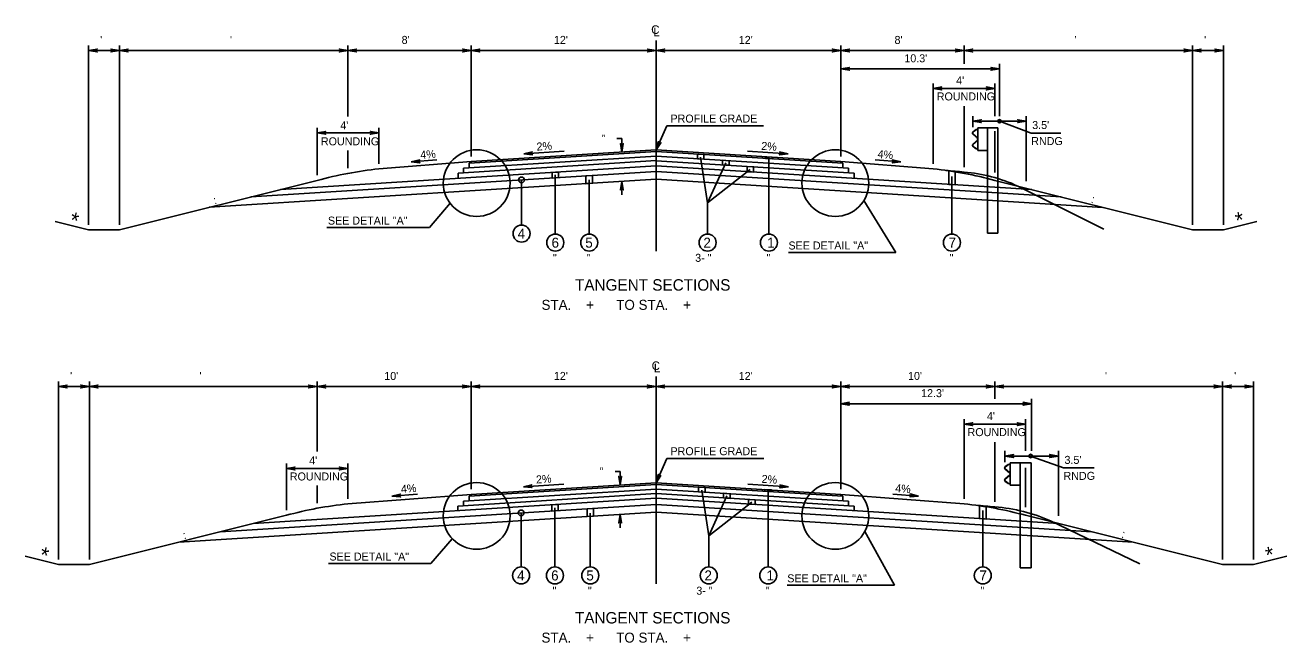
# Model space of a CAD drawing. Extents: x -540 to 1231, y -564 to 421.
# Drawn here: x 173.2 to 393.9, y -310 to -201.9 of the extents above; entities that cross this region are included whole.
import ezdxf

# ---------------------------------------------------------------- set-up
doc = ezdxf.new("R2010")
doc.units = 0
doc.layers.add('1', color=7, linetype='Continuous')
doc.layers.add('Des_ Drain_ Ftrs', color=7, linetype='Continuous')

msp = doc.modelspace()

# ---------------------------------------------------------------- linework, layer by layer
at = {"layer": '1'}
for p, q in [((283.58, -241.47), (283.58, -204.59)), ((184.34, -236.84), (184.34, -205.47)), ((189.73, -206.35), (184.34, -206.35)), ((189.73, -236.84), (189.73, -205.47)), ((229.69, -206.35), (189.73, -206.35)), ((229.69, -217.88), (229.69, -205.47)), ((251.25, -206.35), (229.69, -206.35)), ((251.25, -224.9), (251.25, -205.47)), ((283.58, -206.35), (251.25, -206.35)), ((283.58, -206.35), (315.91, -206.35)), ((315.91, -224.9), (315.91, -205.47)), ((315.91, -206.35), (337.46, -206.35)), ((337.46, -208.69), (337.46, -205.47)), ((337.46, -206.35), (377.42, -206.35)), ((377.42, -236.85), (377.42, -205.47)), ((377.42, -206.35), (382.81, -206.35)), ((382.81, -236.85), (382.81, -205.47)), ((315.9, -209.57), (343.65, -209.57)), ((343.65, -217.85), (343.65, -208.69)), ((332.07, -226.2), (332.07, -212.11)), ((332.07, -212.99), (342.85, -212.99)), ((342.85, -217.85), (342.85, -212.11)), ((337.46, -226.76), (337.46, -216.11)), ((338.96, -219.8), (338.96, -217.85)), ((348.34, -229.21), (348.34, -217.85)), ((224.32, -228.2), (224.32, -219.89)), ((235.09, -226.19), (235.09, -219.89)), ((283.58, -223.75), (285.48, -219.56)), ((302.4, -219.56), (285.48, -219.56)), ((338.96, -218.73), (348.34, -218.73)), ((339.56, -220.19), (339.04, -220.58)), ((339.57, -220.22), (339.06, -220.61)), ((339.87, -220.14), (339.56, -220.19)), ((339.87, -220.17), (339.57, -220.22)), ((339.87, -219.91), (339.87, -223.84)), ((339.87, -219.91), (341.56, -219.91)), ((341.56, -219.91), (341.56, -238.31)), ((343.38, -219.91), (341.56, -219.91)), ((342.85, -227.72), (342.85, -220.48)), ((343.38, -219.91), (343.38, -238.31)), ((343.65, -218.73), (349.21, -220.8)), ((235.09, -220.77), (224.32, -220.77)), ((277.59, -221.75), (276.71, -221.75)), ((277.59, -221.75), (277.59, -224.12)), ((339.02, -221.01), (339.76, -221.65)), ((339.76, -222.1), (339.02, -222.74)), ((339.04, -220.99), (339.78, -221.63)), ((339.78, -222.12), (339.04, -222.76)), ((339.84, -221.84), (339.84, -221.91)), ((339.87, -221.84), (339.87, -221.91)), ((349.21, -220.8), (354.36, -220.8)), ((229.69, -226.97), (229.69, -223.83)), ((249.92, -226.95), (283.58, -224.84)), ((250.89, -226.1), (283.58, -224.04)), ((251.25, -225.77), (283.58, -223.74)), ((267.53, -224), (260.45, -224.44)), ((315.91, -225.78), (283.58, -223.75)), ((316.27, -226.1), (283.58, -224.04)), ((317.24, -226.96), (283.58, -224.84)), ((291.38, -225.04), (292.6, -233.04)), ((299.59, -224), (306.66, -224.45)), ((339.04, -223.17), (339.56, -223.56)), ((339.06, -223.14), (339.57, -223.53)), ((339.56, -223.56), (339.87, -223.61)), ((339.57, -223.53), (339.87, -223.58)), ((339.87, -223.84), (341.56, -223.84)), ((217.88, -230.69), (283.58, -226.56)), ((235.09, -227.07), (251.25, -225.77)), ((240.77, -225.86), (245.26, -225.5)), ((248.94, -227.81), (283.58, -225.63)), ((249.92, -226.95), (249.92, -227.75)), ((250.89, -226.1), (250.89, -226.89)), ((251.25, -226.07), (251.25, -225.77)), ((318.21, -227.82), (283.58, -225.64)), ((349.28, -230.7), (283.58, -226.56)), ((295.79, -226.02), (292.6, -233.04)), ((300.06, -227.2), (292.6, -233.04)), ((303.32, -225.14), (303.32, -238.5)), ((332.07, -227.08), (315.91, -225.78)), ((315.91, -226.08), (315.91, -225.78)), ((316.27, -226.1), (316.27, -226.88)), ((317.24, -226.96), (317.24, -227.75)), ((326.4, -225.86), (321.92, -225.5)), ((224.32, -229.08), (189.73, -237.72)), ((205.41, -233.8), (283.58, -228.89)), ((212.71, -231.98), (283.58, -227.53)), ((248.94, -227.81), (248.94, -228.74)), ((260.06, -229.01), (260.06, -236.91)), ((265.96, -228.12), (265.96, -238.5)), ((271.89, -228.97), (271.89, -238.5)), ((277.59, -229.27), (277.59, -231.64)), ((354.45, -231.99), (283.58, -227.53)), ((361.74, -233.81), (283.58, -228.89)), ((318.21, -227.82), (318.21, -228.74)), ((335.33, -228.42), (335.33, -238.5)), ((338.96, -227.86), (338.96, -227.86)), ((342.85, -229.09), (377.42, -237.73)), ((346.84, -230.09), (361.89, -237.61)), ((243.93, -237.32), (247.58, -233.1)), ((292.6, -233.04), (292.6, -238.5)), ((319.92, -232.6), (325.52, -241.68)), ((178.51, -236.26), (184.34, -237.72)), ((189.73, -237.72), (184.34, -237.72)), ((226, -237.32), (243.93, -237.32)), ((377.42, -237.73), (382.81, -237.73)), ((388.64, -236.27), (382.81, -237.73)), ((343.38, -238.31), (341.56, -238.31)), ((306.73, -241.68), (325.52, -241.68)), ((179.07, -295.43), (179.07, -264.28)), ((184.46, -295.43), (184.46, -264.28)), ((224.3, -276.52), (224.3, -264.28)), ((251.24, -283.15), (251.24, -264.28)), ((283.57, -299.71), (283.57, -263.4)), ((315.9, -283.15), (315.9, -264.28)), ((342.84, -267.29), (342.84, -264.28)), ((382.68, -295.43), (382.68, -264.28)), ((388.07, -295.43), (388.07, -264.28)), ((184.46, -265.16), (179.07, -265.16)), ((224.3, -265.16), (184.46, -265.16)), ((251.24, -265.16), (224.3, -265.16)), ((283.57, -265.16), (251.24, -265.16)), ((283.57, -265.16), (315.9, -265.16)), ((315.9, -265.16), (342.84, -265.16)), ((342.84, -265.16), (382.68, -265.16)), ((382.68, -265.16), (388.07, -265.16)), ((315.89, -268.17), (349.26, -268.17)), ((349.26, -276.44), (349.26, -267.29)), ((337.45, -284.81), (337.45, -270.86)), ((348.22, -276.44), (348.22, -270.86)), ((337.45, -271.74), (348.22, -271.74)), ((342.84, -285.35), (342.84, -274.89)), ((283.57, -281.99), (285.49, -277.76)), ((302.41, -277.76), (285.49, -277.76)), ((344.57, -278.39), (344.57, -276.44)), ((344.57, -277.32), (353.96, -277.32)), ((349.09, -277.32), (354.85, -279.4)), ((353.96, -287.81), (353.96, -276.44)), ((218.92, -286.82), (218.92, -278.62)), ((229.69, -279.5), (218.92, -279.5)), ((229.69, -284.81), (229.69, -278.62)), ((277.31, -280.02), (276.43, -280.02)), ((277.31, -280.02), (277.31, -282.39)), ((344.64, -279.61), (345.4, -280.25)), ((345.19, -278.79), (344.66, -279.18)), ((344.66, -279.59), (345.42, -280.23)), ((345.2, -278.82), (344.67, -279.2)), ((345.52, -278.74), (345.19, -278.79)), ((345.52, -278.77), (345.2, -278.82)), ((345.52, -278.51), (345.52, -282.44)), ((345.52, -278.51), (347.27, -278.51)), ((347.27, -278.51), (347.27, -296.9)), ((349.16, -278.51), (347.27, -278.51)), ((348.22, -286.27), (348.22, -279.39)), ((349.16, -278.51), (349.16, -296.9)), ((354.85, -279.4), (360.2, -279.4)), ((250.87, -284.35), (283.57, -282.29)), ((251.23, -284.03), (283.57, -281.99)), ((267.44, -282.25), (260.37, -282.69)), ((315.9, -284.03), (283.57, -281.99)), ((316.26, -284.35), (283.57, -282.29)), ((299.64, -282.27), (306.72, -282.72)), ((345.4, -280.7), (344.64, -281.33)), ((345.42, -280.72), (344.66, -281.36)), ((344.66, -281.77), (345.19, -282.16)), ((344.67, -281.74), (345.2, -282.13)), ((345.19, -282.16), (345.52, -282.21)), ((345.2, -282.13), (345.52, -282.18)), ((345.49, -280.44), (345.49, -280.51)), ((345.52, -280.44), (345.52, -280.51)), ((224.3, -285.59), (224.3, -282.47)), ((229.69, -285.69), (251.23, -284.03)), ((237.38, -284.33), (241.87, -283.98)), ((248.89, -286.09), (283.57, -283.91)), ((249.88, -285.22), (283.57, -283.1)), ((250.87, -284.35), (250.87, -285.16)), ((251.23, -284.33), (251.23, -284.03)), ((317.25, -285.22), (283.57, -283.1)), ((318.24, -286.09), (283.57, -283.91)), ((291.58, -283.32), (292.8, -291.3)), ((292.15, -282.83), (292.15, -283.64)), ((295.97, -284.3), (292.8, -291.3)), ((303.2, -283.35), (303.2, -296.74)), ((315.9, -284.33), (315.9, -284.03)), ((337.45, -285.69), (315.9, -284.03)), ((316.26, -284.35), (316.26, -285.16)), ((329.49, -284.32), (325, -283.98)), ((345.52, -282.44), (347.27, -282.44)), ((207.35, -290.59), (283.57, -285.8)), ((213.12, -289.15), (283.57, -284.72)), ((248.89, -286.09), (248.89, -286.9)), ((249.88, -285.22), (249.88, -286.03)), ((265.9, -286.41), (265.9, -296.74)), ((354.02, -289.15), (283.57, -284.72)), ((359.79, -290.59), (283.57, -285.8)), ((300.34, -285.39), (292.8, -291.3)), ((317.25, -285.22), (317.25, -286.04)), ((318.24, -286.09), (318.24, -286.91)), ((344.57, -286.45), (344.57, -286.45)), ((218.92, -287.7), (184.46, -296.31)), ((200.14, -292.39), (283.57, -287.15)), ((259.97, -287.28), (259.97, -296.74)), ((272.08, -287.33), (272.08, -296.74)), ((277.31, -287.54), (277.31, -289.91)), ((367, -292.39), (283.57, -287.15)), ((340.73, -286.86), (340.73, -296.74)), ((348.22, -287.7), (382.68, -296.31)), ((352.58, -288.69), (368.19, -296.21)), ((320.1, -290.51), (325.3, -299.94)), ((244.2, -296.12), (247.94, -291.8)), ((292.8, -291.3), (292.8, -296.74)), ((173.25, -294.85), (179.07, -296.31)), ((393.89, -294.86), (388.07, -296.31)), ((184.46, -296.31), (179.07, -296.31)), ((226.27, -296.12), (244.2, -296.12)), ((349.16, -296.9), (347.27, -296.9)), ((382.68, -296.31), (388.07, -296.31)), ((306.52, -299.94), (325.3, -299.94))]:
    msp.add_line(p, q, dxfattribs=at)
for points in [[(290.81, -224.5), (291.96, -224.57), (291.96, -225.37), (290.81, -225.29)], [(302.75, -224.95), (303.89, -225.03), (303.89, -225.32), (302.75, -225.25)], [(295.22, -225.57), (296.36, -225.64), (296.36, -226.44), (295.22, -226.37)], [(299.49, -226.64), (300.64, -226.71), (300.64, -227.64), (299.49, -227.57)], [(265.39, -227.7), (266.54, -227.63), (266.54, -228.6), (265.39, -228.67)], [(271.32, -229.66), (271.32, -228.3), (272.47, -228.23), (272.47, -229.59)], [(334.76, -227.41), (335.91, -227.59), (335.91, -229.86), (334.76, -229.78)], [(291.01, -282.76), (292.15, -282.83), (292.15, -283.64), (291.01, -283.57)], [(295.39, -283.85), (296.54, -283.92), (296.54, -284.73), (295.39, -284.66)], [(302.63, -283.19), (303.78, -283.26), (303.78, -283.56), (302.63, -283.49)], [(265.33, -285.87), (266.47, -285.79), (266.47, -286.87), (265.33, -286.95)], [(271.51, -286.56), (272.65, -286.49), (272.65, -287.83), (271.51, -287.91)], [(299.77, -284.93), (300.92, -285), (300.92, -285.81), (299.77, -285.74)], [(340.15, -286.03), (341.3, -286.2), (341.3, -288.35), (340.15, -288.28)]]:
    msp.add_lwpolyline(points, close=True, dxfattribs=at)
for centre, radius in [((343.65, -218.73), 0.3), ((252.21, -229.56), 5.84), ((314.94, -229.56), 5.84), ((260.06, -229.01), 0.5), ((260.06, -238.4), 1.49), ((265.96, -239.98), 1.49), ((271.89, -239.98), 1.49), ((292.6, -239.98), 1.49), ((303.32, -239.98), 1.49), ((335.33, -239.98), 1.49), ((252.2, -287.8), 5.84), ((314.93, -287.8), 5.84), ((259.97, -287.28), 0.5), ((259.97, -298.23), 1.49), ((265.9, -298.23), 1.49), ((272.08, -298.23), 1.49), ((292.8, -298.23), 1.49), ((303.2, -298.23), 1.49), ((340.73, -298.23), 1.49)]:
    msp.add_circle(centre, radius, dxfattribs=at)
for centre, radius, start, end in [((339.21, -220.8), 0.278, 126.9799, 229.021), ((339.21, -220.8), 0.249, 126.9799, 229.021), ((339.21, -222.95), 0.278, 130.979, 233.0201), ((339.21, -222.95), 0.249, 130.979, 233.0201), ((339.59, -221.84), 0.249, 0, 49.0365), ((339.59, -221.91), 0.249, 310.9635, 0), ((339.59, -221.84), 0.278, 0, 49.0365), ((339.59, -221.91), 0.278, 310.9635, 0), ((241.98, -293.91), 67.19, 95.8795, 105.2381), ((325.19, -293.91), 67.19, 74.7619, 84.1205), ((326.64, -328.3), 101.24, 83.8633, 85.6775), ((335.34, -254.92), 27.37, 65.1374, 85.5513), ((236.58, -352.53), 67.19, 95.8795, 105.2381), ((330.56, -352.53), 67.19, 74.7598, 84.1183)]:
    msp.add_arc(centre, radius, start, end, dxfattribs=at)
msp.add_ellipse((349.09, -277.32), major_axis=(-0.311, 0), ratio=0.964041, dxfattribs=at)
for centre, major_axis, start_param, end_param in [((344.83, -279.4), (-0.288, 0), 5.35781, 7.138763), ((344.83, -279.4), (-0.258, 0), 5.35781, 7.138763), ((344.83, -281.54), (-0.288, 0), 5.427608, 7.208561), ((344.83, -281.54), (-0.258, 0), 5.427608, 7.208561), ((345.23, -280.44), (0.258, 0), 0, 0.855848), ((345.23, -280.51), (0.258, 0), 5.427337, 6.283185), ((345.23, -280.44), (0.288, 0), 0, 0.855848), ((345.23, -280.51), (0.288, 0), 5.427337, 6.283185), ((331.61, -386.9), (105.02, 0), 1.463691, 1.495354), ((340.64, -313.52), (28.39, 0), 1.136862, 1.493152)]:
    msp.add_ellipse(centre, major_axis=major_axis, ratio=0.964041, start_param=start_param, end_param=end_param, dxfattribs=at)
at = {"layer": 'Des_ Drain_ Ftrs'}
for points in [[(184.34, -206.35), (185.83, -206.6), (185.53, -206.35), (185.83, -206.11)], [(189.73, -206.35), (188.24, -206.6), (188.54, -206.35), (188.24, -206.11)], [(189.73, -206.35), (191.22, -206.6), (190.92, -206.35), (191.22, -206.11)], [(229.69, -206.35), (228.21, -206.6), (228.5, -206.35), (228.21, -206.11)], [(229.69, -206.35), (231.18, -206.6), (230.89, -206.35), (231.18, -206.11)], [(251.25, -206.35), (249.76, -206.6), (250.05, -206.35), (249.76, -206.11)], [(251.25, -206.35), (252.74, -206.6), (252.44, -206.35), (252.74, -206.11)], [(283.58, -206.35), (282.09, -206.6), (282.38, -206.35), (282.09, -206.11)], [(283.58, -206.35), (285.07, -206.6), (284.77, -206.35), (285.07, -206.11)], [(315.91, -206.35), (314.42, -206.6), (314.71, -206.35), (314.42, -206.11)], [(315.91, -206.35), (317.39, -206.6), (317.1, -206.35), (317.39, -206.11)], [(337.46, -206.35), (335.97, -206.6), (336.27, -206.35), (335.97, -206.11)], [(337.46, -206.35), (338.95, -206.6), (338.65, -206.35), (338.95, -206.11)], [(377.42, -206.35), (375.93, -206.6), (376.23, -206.35), (375.93, -206.11)], [(377.42, -206.35), (378.91, -206.6), (378.61, -206.35), (378.91, -206.11)], [(382.81, -206.35), (381.32, -206.6), (381.62, -206.35), (381.32, -206.11)], [(315.9, -209.57), (317.39, -209.82), (317.09, -209.57), (317.39, -209.32)], [(343.65, -209.57), (342.16, -209.82), (342.46, -209.57), (342.16, -209.32)], [(332.07, -212.99), (333.56, -213.24), (333.26, -212.99), (333.56, -212.74)], [(342.85, -212.99), (341.36, -213.24), (341.65, -212.99), (341.36, -212.74)], [(224.32, -220.77), (225.81, -221.02), (225.51, -220.77), (225.81, -220.52)], [(235.09, -220.77), (233.61, -221.02), (233.9, -220.77), (233.61, -220.52)], [(338.96, -218.73), (340.45, -218.97), (340.15, -218.73), (340.45, -218.48)], [(348.34, -218.73), (346.85, -218.97), (347.15, -218.73), (346.85, -218.48)], [(277.59, -224.12), (277.84, -222.63), (277.59, -222.93), (277.34, -222.63)], [(283.58, -223.75), (284.42, -222.5), (284.07, -222.66), (283.97, -222.29)], [(260.45, -224.44), (261.95, -224.6), (261.64, -224.37), (261.92, -224.1)], [(306.66, -224.45), (305.16, -224.6), (305.47, -224.37), (305.19, -224.11)], [(240.77, -225.86), (242.28, -225.99), (241.96, -225.76), (242.24, -225.49)], [(326.4, -225.86), (324.9, -225.99), (325.21, -225.77), (324.93, -225.5)], [(277.59, -229.27), (277.84, -230.76), (277.59, -230.47), (277.34, -230.76)], [(179.07, -265.16), (180.56, -265.41), (180.27, -265.16), (180.56, -264.92)], [(184.46, -265.16), (182.97, -265.41), (183.27, -265.16), (182.97, -264.92)], [(184.46, -265.16), (185.95, -265.41), (185.65, -265.16), (185.95, -264.92)], [(224.3, -265.16), (222.81, -265.41), (223.1, -265.16), (222.81, -264.92)], [(224.3, -265.16), (225.78, -265.41), (225.49, -265.16), (225.78, -264.92)], [(251.24, -265.16), (249.75, -265.41), (250.04, -265.16), (249.75, -264.92)], [(251.24, -265.16), (252.73, -265.41), (252.43, -265.16), (252.73, -264.92)], [(283.57, -265.16), (282.08, -265.41), (282.37, -265.16), (282.08, -264.92)], [(283.57, -265.16), (285.05, -265.41), (284.76, -265.16), (285.05, -264.92)], [(315.9, -265.16), (314.41, -265.41), (314.7, -265.16), (314.41, -264.92)], [(315.9, -265.16), (317.38, -265.41), (317.09, -265.16), (317.38, -264.92)], [(342.84, -265.16), (341.35, -265.41), (341.64, -265.16), (341.35, -264.92)], [(342.84, -265.16), (344.33, -265.41), (344.03, -265.16), (344.33, -264.92)], [(382.68, -265.16), (381.19, -265.41), (381.48, -265.16), (381.19, -264.92)], [(382.68, -265.16), (384.17, -265.41), (383.87, -265.16), (384.17, -264.92)], [(388.07, -265.16), (386.58, -265.41), (386.87, -265.16), (386.58, -264.92)], [(315.89, -268.17), (317.38, -268.42), (317.09, -268.17), (317.38, -267.92)], [(349.26, -268.17), (347.77, -268.42), (348.07, -268.17), (347.77, -267.92)], [(337.45, -271.74), (338.94, -271.99), (338.64, -271.74), (338.94, -271.49)], [(348.22, -271.74), (346.74, -271.99), (347.03, -271.74), (346.74, -271.49)], [(344.57, -277.32), (346.12, -277.57), (345.81, -277.32), (346.12, -277.08)], [(353.96, -277.32), (352.41, -277.57), (352.72, -277.32), (352.41, -277.08)], [(218.92, -279.5), (220.41, -279.75), (220.11, -279.5), (220.41, -279.25)], [(229.69, -279.5), (228.21, -279.75), (228.5, -279.5), (228.21, -279.25)], [(260.37, -282.69), (261.87, -282.85), (261.56, -282.62), (261.84, -282.35)], [(277.31, -282.39), (277.56, -280.9), (277.31, -281.19), (277.06, -280.9)], [(283.57, -281.99), (284.41, -280.74), (284.06, -280.91), (283.96, -280.54)], [(306.72, -282.72), (305.22, -282.87), (305.53, -282.64), (305.25, -282.38)], [(237.38, -284.33), (238.89, -284.47), (238.57, -284.24), (238.85, -283.97)], [(329.49, -284.32), (327.99, -284.46), (328.3, -284.23), (328.02, -283.96)], [(277.31, -287.54), (277.56, -289.03), (277.31, -288.73), (277.06, -289.03)]]:
    msp.add_lwpolyline(points, close=True, dxfattribs=at)

# ---------------------------------------------------------------- texts
at = {"layer": '1'}
for s, height, p in [(" '", 1.4, (185.84, -205.2)), ("  '", 1.4, (208.02, -205.2)), ("8'", 1.4, (239.08, -205.2)), ("12'", 1.4, (265.72, -205.2)), ("12'", 1.4, (298.05, -205.2)), ("8'", 1.4, (325.29, -205.2)), ("  '", 1.4, (355.74, -205.2)), (" '", 1.4, (378.92, -205.2)), ("10.3'", 1.4, (327.01, -208.42)), ("4'", 1.4, (336.07, -212.29)), ('ROUNDING', 1.4, (332.68, -215.09)), ('PROFILE GRADE', 1.4, (286.1, -218.97)), ("4'", 1.4, (228.35, -220.15)), ("3.5'", 1.4, (349.37, -220.1)), ('ROUNDING', 1.4, (224.96, -222.95)), ('RNDG', 1.4, (349.2, -222.9)), ('SEE DETAIL "A"', 1.4, (226.19, -236.82)), ('4', 1.75, (259.38, -239.27)), ('6', 1.75, (265.3, -240.86)), ('5', 1.75, (271.2, -240.86)), ('2', 1.75, (291.86, -240.86)), ('1', 1.75, (303.02, -240.86)), ('SEE DETAIL "A"', 1.4, (306.74, -241.18)), ('7', 1.75, (334.74, -240.86)), (' "', 1.4, (265.02, -243.34)), (' "', 1.4, (270.95, -243.34)), ('3- "', 1.4, (290.42, -243.34)), (' "', 1.4, (302.38, -243.34)), ('  "', 1.4, (333.89, -243.34)), ('TANGENT SECTIONS', 2, (269.4, -248.38)), ('STA.    +      TO STA.    +     ', 1.75, (263.55, -251.74)), (" '", 1.4, (180.57, -264.01)), ("  '", 1.4, (202.68, -264.01)), ("10'", 1.4, (236.05, -264.01)), ("12'", 1.4, (265.71, -264.01)), ("12'", 1.4, (298.04, -264.01)), ("10'", 1.4, (327.65, -264.01)), ("  '", 1.4, (361.06, -264.01)), (" '", 1.4, (384.18, -264.01)), ("12.3'", 1.4, (329.94, -267.02)), ("4'", 1.4, (341.45, -271.04)), ('ROUNDING', 1.4, (338.06, -273.84)), ('PROFILE GRADE', 1.4, (286.1, -277.18)), ("4'", 1.4, (222.92, -278.8)), ("3.5'", 1.4, (355.02, -278.7)), ('ROUNDING', 1.4, (219.53, -281.6)), ('RNDG', 1.4, (354.84, -281.5)), ('SEE DETAIL "A"', 1.4, (226.46, -295.61)), ('4', 1.75, (259.29, -299.1)), ('6', 1.75, (265.23, -299.1)), ('5', 1.75, (271.39, -299.1)), ('2', 1.75, (292.05, -299.1)), ('1', 1.75, (302.9, -299.1)), ('7', 1.75, (340.14, -299.1)), ('SEE DETAIL "A"', 1.4, (306.53, -299.43)), (' "', 1.4, (264.96, -301.59)), (' "', 1.4, (271.14, -301.59)), ('3- "', 1.4, (290.62, -301.59)), (' "', 1.4, (302.26, -301.59)), ('  "', 1.4, (339.28, -301.59)), ('TANGENT SECTIONS', 2, (269.39, -306.63)), ('STA.    +      TO STA.    +     ', 1.75, (263.54, -309.98))]:
    msp.add_text(s, height=height, dxfattribs=at).set_placement(p)
for s, height, rotation, p in [('2%', 1.4, 3.7237, (262.72, -223.88)), ('  "', 1.4, 0.1438, (272.98, -222.46)), ('2%', 1.4, 356.2763, (301.95, -223.73)), ('4%', 1.4, 4.869, (242.4, -225.34)), ('4%', 1.4, 355.1254, (322.29, -225.14)), (' : ', 1.4, 14.2282, (205.84, -233.41)), (' : ', 1.4, 345.7718, (359.08, -232.86)), ('*', 2.8, 347.1521, (180.83, -237.29)), ('*', 2.8, 12.8479, (385.27, -237.54)), ('  "', 1.4, 0.1438, (272.7, -280.72)), ('4%', 1.4, 4.7023, (239.01, -283.82)), ('2%', 1.4, 3.7237, (262.63, -282.14)), ('2%', 1.4, 356.2769, (302.01, -282)), ('4%', 1.4, 355.2923, (325.37, -283.61)), (' : ', 1.4, 14.2282, (200.51, -292.02)), (' : ', 1.4, 345.7718, (364.4, -291.46)), ('*', 2.8, 347.1521, (175.56, -295.88)), ('*', 2.8, 12.8479, (390.53, -296.12))]:
    msp.add_text(s, height=height, rotation=rotation, dxfattribs=at).set_placement(p)
at = {"layer": 'Des_ Drain_ Ftrs'}
for s, p in [('C', (282.73, -203.45)), ('L', (283.12, -203.85)), ('C', (282.81, -262.27)), ('L', (283.2, -262.67))]:
    msp.add_text(s, height=1.5, dxfattribs=at).set_placement(p)

doc.saveas('drawing.dxf')
